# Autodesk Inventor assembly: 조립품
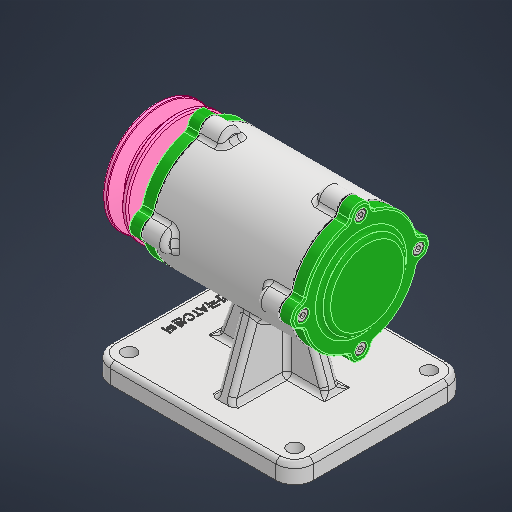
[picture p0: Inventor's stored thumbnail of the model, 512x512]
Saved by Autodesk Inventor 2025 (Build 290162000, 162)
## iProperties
Created: 2025-08
Part Number: 조립품
Document SubType Name: Assembly
Designer: infra006
Author: infra006
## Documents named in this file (12)
- C:\Users\infra006\Desktop\750806V1011\조립품.iam
- C:\Users\infra006\Desktop\시험5\공용부품_20250517_2 (3)\앞커버\앞커버.ipt
- C:\Users\infra006\Desktop\시험5\공용부품_20250517_2 (3)\오일 실\오일 실.ipt
- C:\Users\infra006\Desktop\시험5\공용부품_20250517_2 (3)\축\축.ipt
- C:\Users\infra006\Desktop\시험5\공용부품_20250517_2 (3)\키 4 x 4\키 4 x 4.ipt
- C:\Users\infra006\Desktop\시험5\공용부품_20250517_2 (3)\V-벨트풀리\V-벨트풀리.ipt
- C:\Users\infra006\Desktop\시험5\공용부품_20250517_2 (3)\개스킷\개스킷.ipt
- C:\Users\infra006\Desktop\시험5\공용부품_20250517_2 (3)\너트 M12 x 1.25\너트 M12 x 1.25.ipt
- C:\Users\infra006\Desktop\시험5\공용부품_20250517_2 (3)\뒤커버\뒤커버.ipt
- C:\Users\infra006\Desktop\시험5\공용부품_20250517_2 (3)\베어링 6204\베어링 6204.ipt
- C:\Users\infra006\Desktop\시험5\공용부품_20250517_2 (3)\볼트 M4 x 12\볼트 M4 x 12.ipt
- C:\Users\infra006\Desktop\750806V1011\본체.ipt
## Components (3 placed, 2 different names)
1. V-벨트풀리:1
2. 개스킷:1
3. 개스킷:2
